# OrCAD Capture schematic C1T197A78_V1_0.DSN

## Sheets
1 01_Log: title: Telink-Semi; rev: V1.0; note: C1T197A78
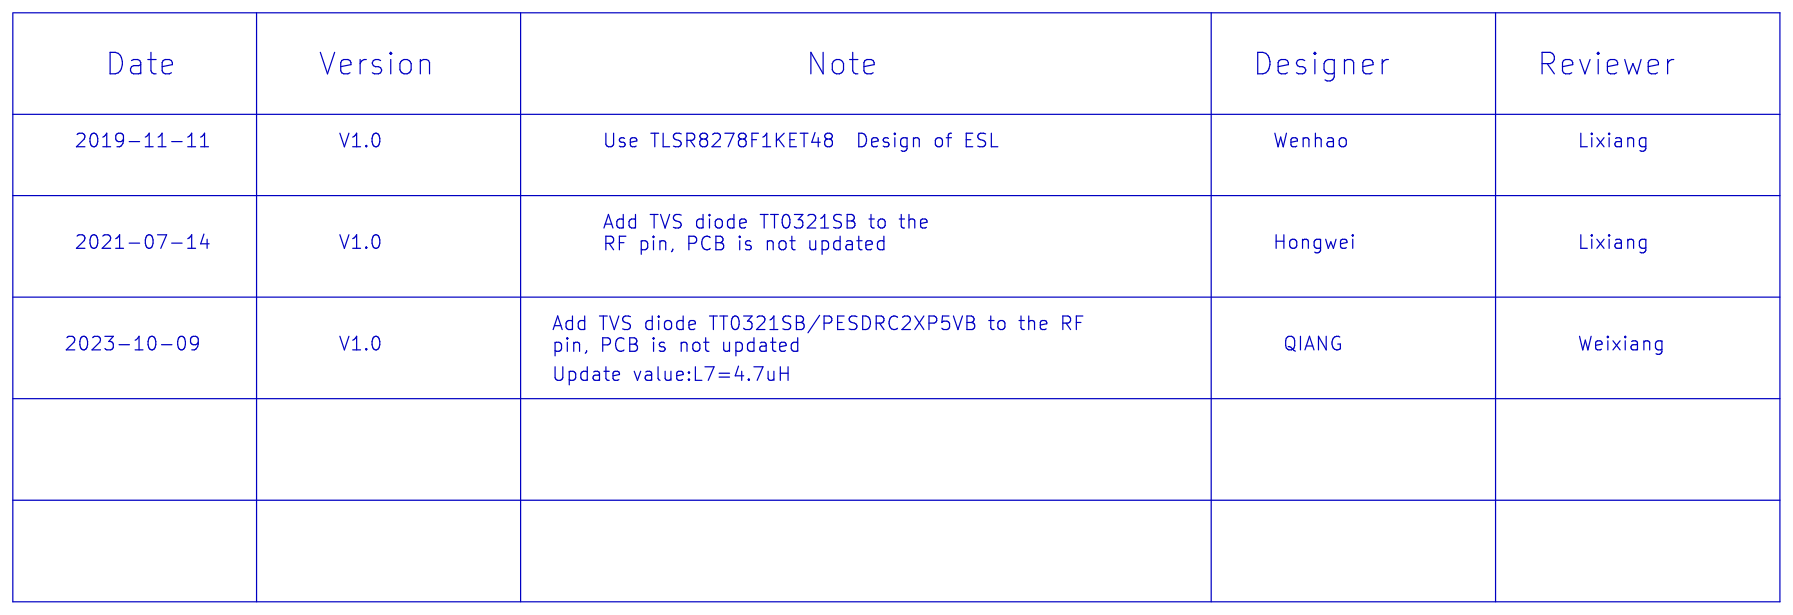
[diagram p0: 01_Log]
2 02_Main: size A4
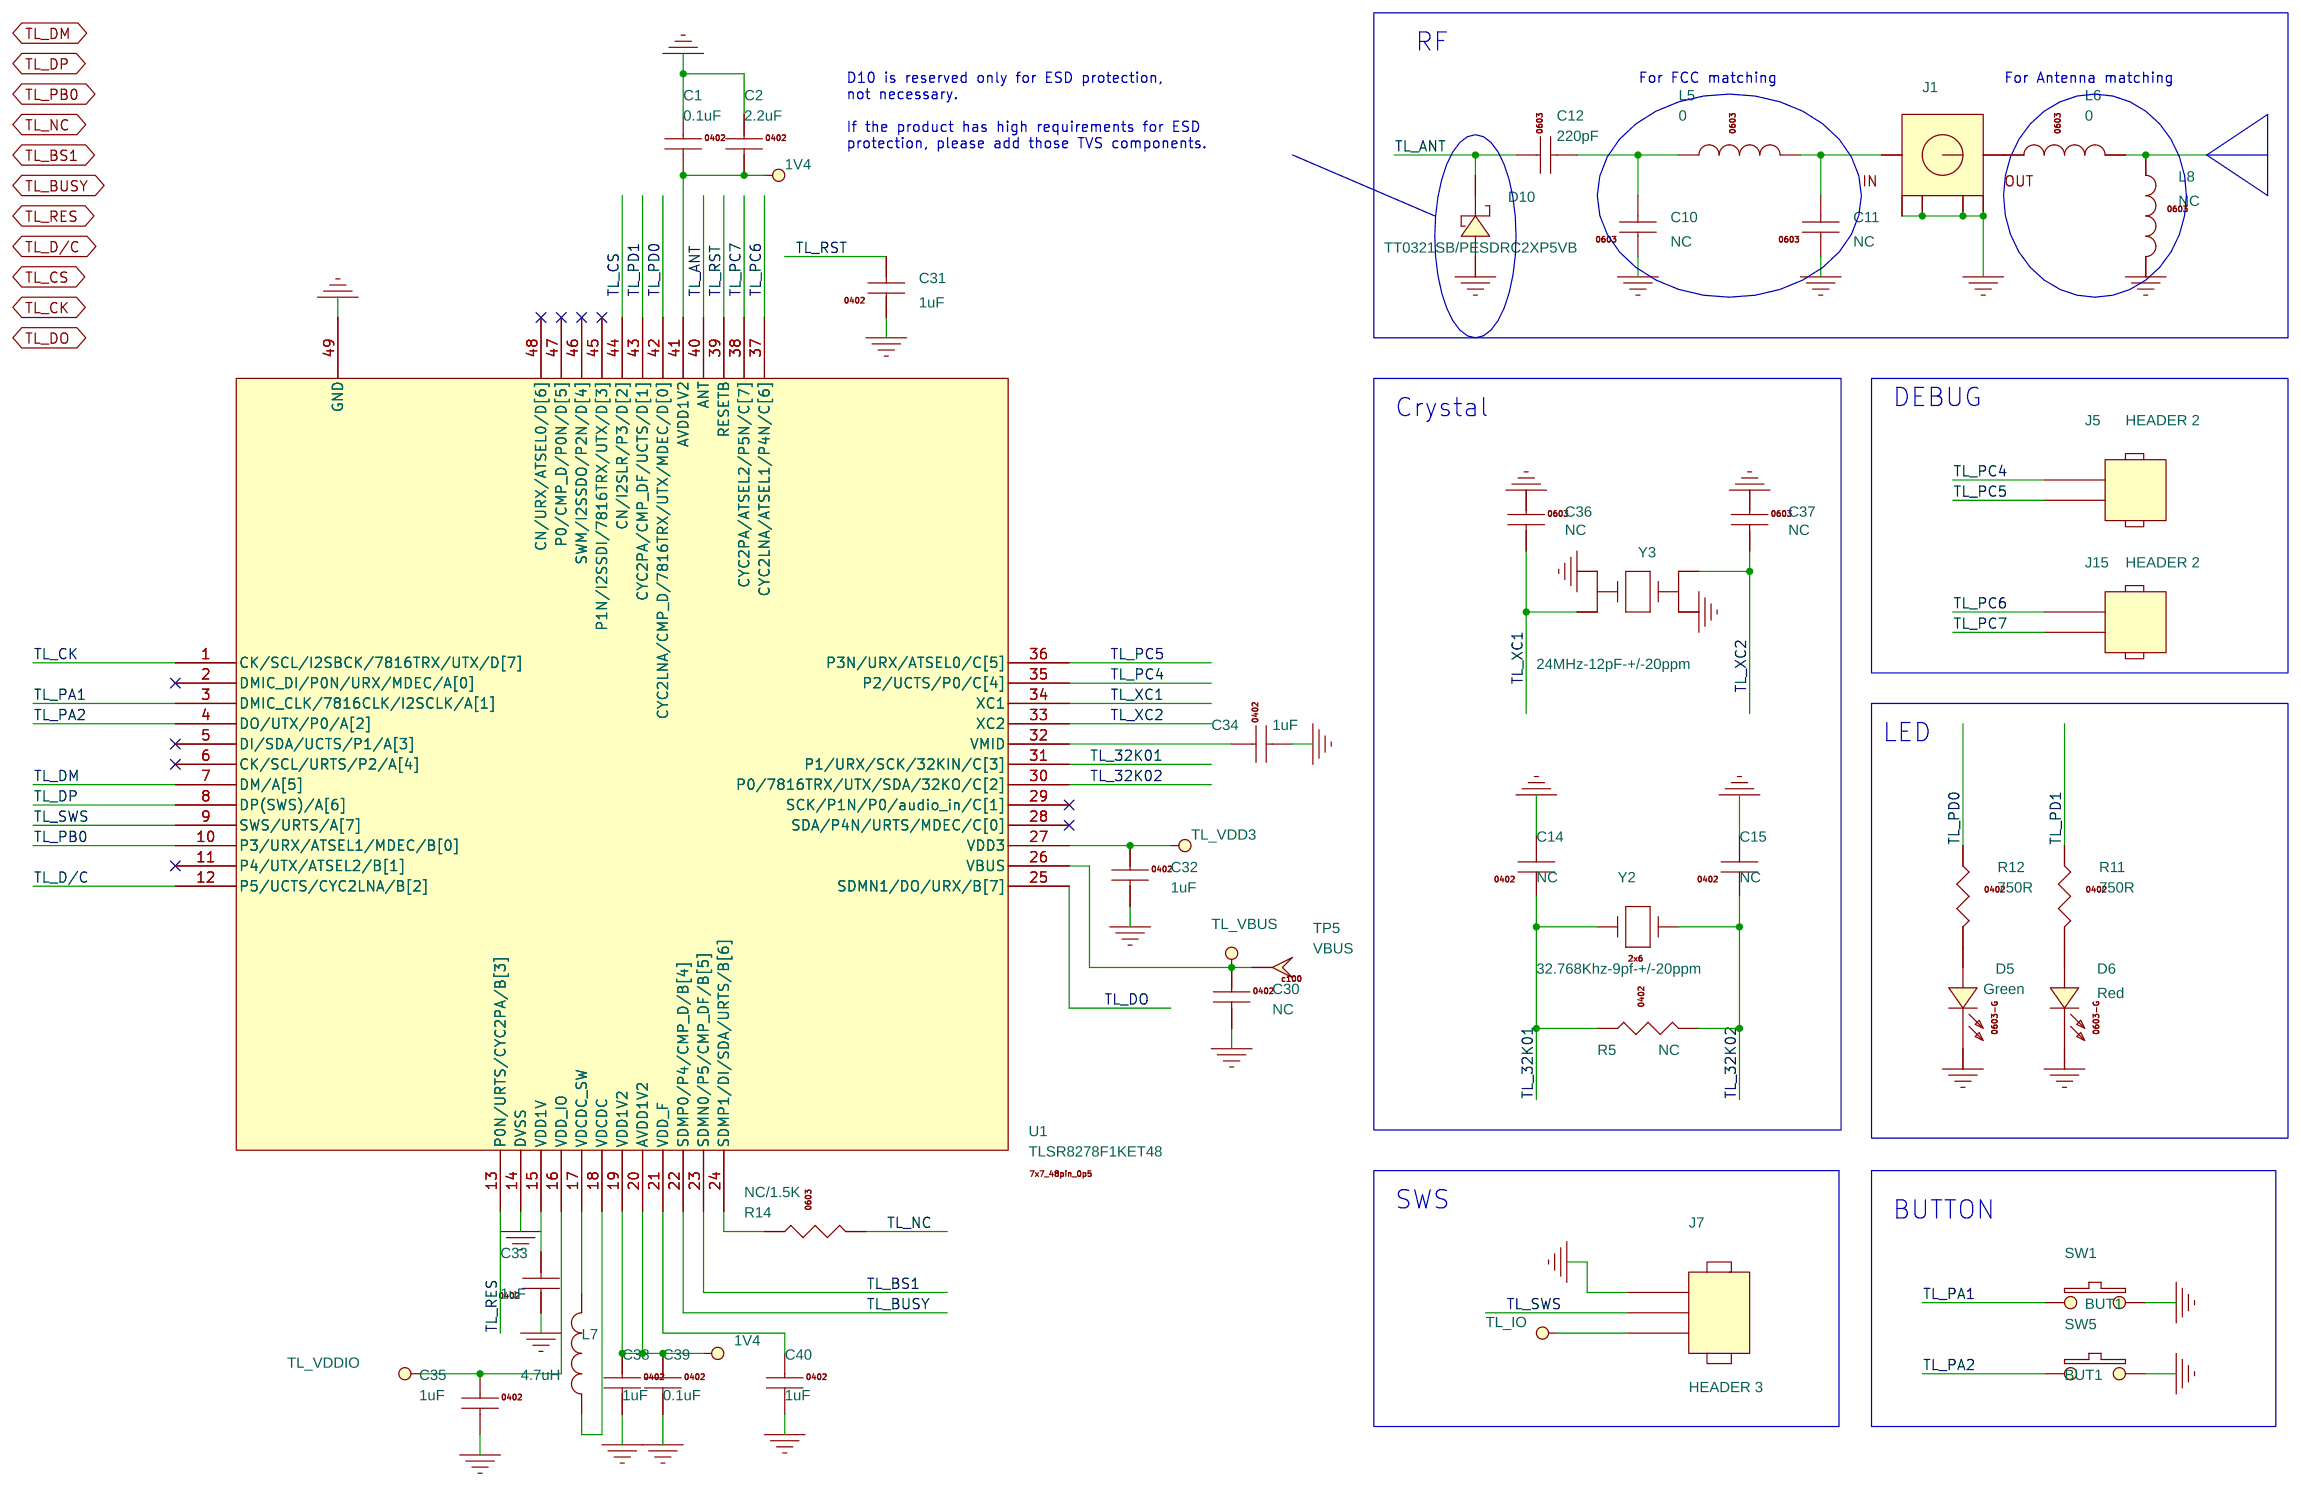
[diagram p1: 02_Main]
3 03_Display: size A4
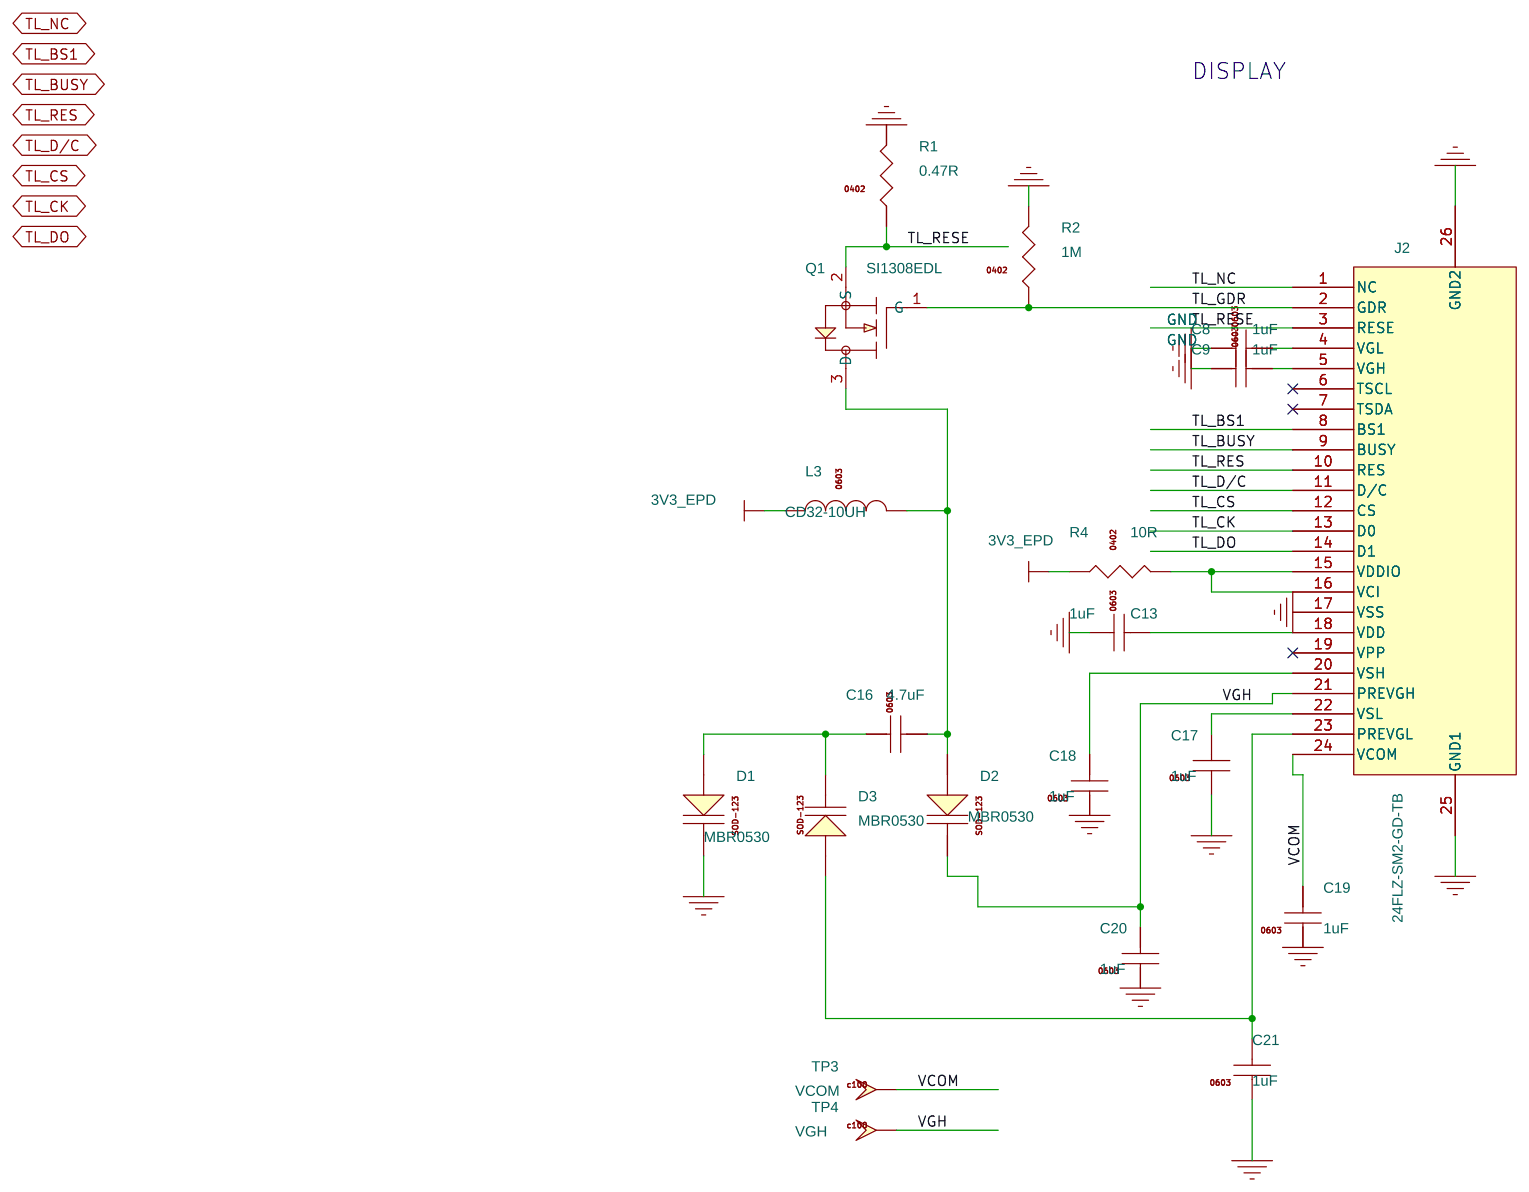
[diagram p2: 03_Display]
4 04_Power: size A4
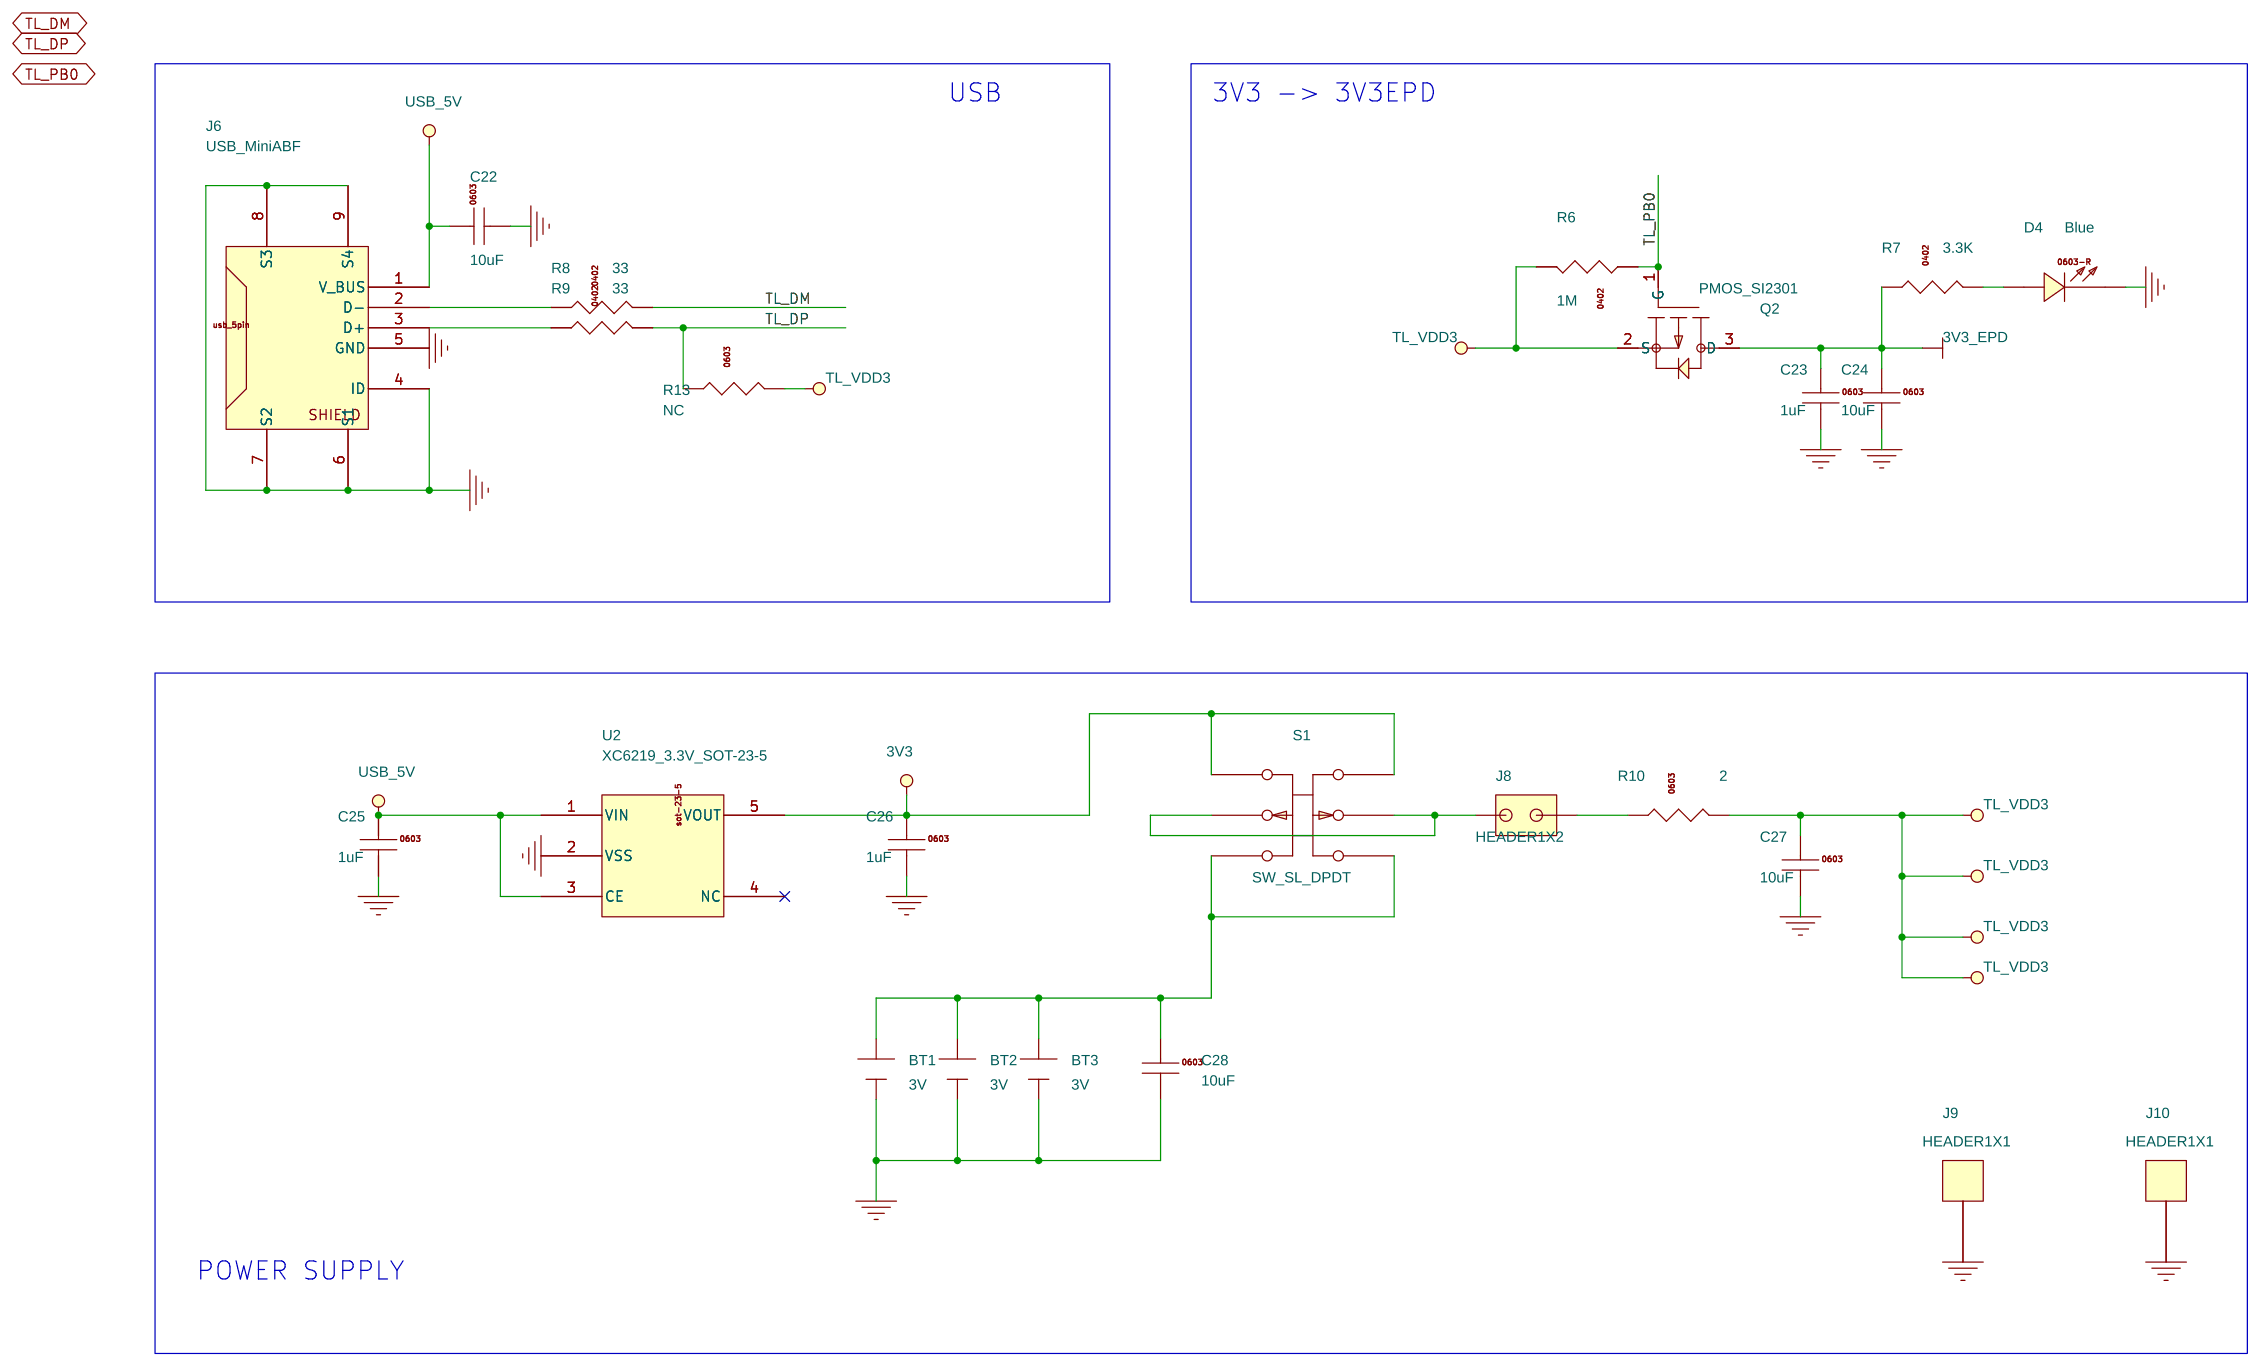
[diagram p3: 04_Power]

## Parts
sheet 02_Main
C1  0.1uF  [0402]
C2  2.2uF  [0402]
C10  NC  [0402]
C11  NC  [0402]
C12  220pF  [0402]
C14  NC  [0402]
C15  NC  [0402]
C30  NC  [0402]
C31  1uF  [0402]
C32  1uF  [0402]
C33  1uF  [0402]
C34  1uF  [0402]
C35  1uF  [0402]
C36  NC  [0402]
C37  NC  [0402]
C38  1uF  [0402]
C39  0.1uF  [0402]
C40  1uF  [0402]
D5  Green  [0603-LED]
D6  Red  [0603-LED]
D10  TT0321SB/PESDRC2XP5VB  [SOD-123]
J1  MM8130  [MM8130-2600]
J5  HEADER 2  [HDR254F-1X2X850]
J7  HEADER 3  [HDR254F-1X3X850]
J15  HEADER 2  [HDR254F-1X2X850]
L5  0  [0402]
L6  0  [0402]
L7  4.7uH  [2x2_5mm]
L8  NC  [0402]
R5  NC  [0402]
R11  750R  [0402]
R12  750R  [0402]
R14  NC/1.5K  [0402]
SW1  BUT1  [butsmd2px4_00y3_00_nh]
SW5  BUT1  [butsmd2px4_00y3_00_nh]
TP5  VBUS  [TP100]
U1  TLSR8278F1KET48  [qfn_7x7_48pin_0p5_4p20x4p20]
Y2  32.768Khz-9pf-+/-20ppm  [OSC_2x6]
Y3  24MHz-12pF-+/-20ppm  [OSCCC250X320X110]
sheet 03_Display
C8  1uF  [0603C]
C9  1uF  [0603C]
C13  1uF  [0402]
C16  4.7uF  [0805C]
C17  1uF  [0603C]
C18  1uF  [0603C]
C19  1uF  [0603C]
C20  1uF  [0603C]
C21  1uF  [0603C]
D1  MBR0530  [sod-123]
D2  MBR0530  [sod-123]
D3  MBR0530  [sod-123]
J2  24FLZ-SM2-GD-TB  [fpc_24pin]
L3  CD32-10UH  [cd32]
Q1  SI1308EDL  [sot-323]
R1  0.47R  [0603r]
R2  1M  [0402]
R4  10R  [0402]
TP3  VCOM  [TP100]
TP4  VGH  [TP100]
sheet 04_Power
BT1  3V  [BAT]
BT2  3V  [BAT]
BT3  3V  [BAT]
C22  10uF  [0603C]
C23  1uF  [0603C]
C24  10uF  [0603C]
C25  1uF  [0603C]
C26  1uF  [0402]
C27  10uF  [0603C]
C28  10uF  [0805C]
D4  Blue  [0603-LED]
J6  USB_MiniABF  [USB-MINI-F5]
J8  HEADER1X2  [HDR254F-1X2X850]
J9  HEADER1X1  [HDR254F-1X1X850]
J10  HEADER1X1  [HDR254F-1X1X850]
Q2  PMOS_SI2301  [mos_sot-23]
R6  1M  [0603r]
R7  3.3K  [0603r]
R8  33  [0402]
R9  33  [0402]
R10  2  [0603R]
R13  NC  [0402]
S1  SW_SL_DPDT  [sw]
U2  XC6219_3.3V_SOT-23-5  [sot-23-5]

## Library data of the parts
C1 C2 C14 C15 C30 C32 C34 C35 C38-C40 = C1005X5R1C104K
C10-C13 C16-C21 C36 C37 = C1608_NC
C31 C33 = C1005X5R1C105K
D5 D6 = 0603D_Green
D10 = DIODE_SCHOTTKY_0
J1 = MM8130_1
J5 J15 = HEADER_2
J7 = HEADER_3
L5 L6 L8 = MLK1608_000R
L7 = IND_0
R5 = RS0402_NC
R11 R12 = RS0402K102JT
R13 R14 = RS0603K152JT
SW1 SW5 = SW_PUSHBUTTON-SPST_SM
TP3-TP5 = TestPad100
U1 = TLSR8278F1KET48_2
Y2 = OSC_2x6_2pin
Y3 = CRYSTAL4_SM_0
C8 C9 C22-C26 = C1608X5R1C105M
D1-D3 = Diode_CDBW0520L-G
J2 = CON_2.54mm_1x24
L3 = MLK1608S4N7ST
Q1 = NMOS_SI2302
R1 R2 R4 = RS0402K000JT
BT1-BT3 = BATTERY_2xAAA_1
C27 C28 = C1608X5R0J106M
D4 = 0603D_Red
J6 = USB_MiniABF_5pin
J8 = B2S_3: PAGE: POWER
J9 J10 = CON1
Q2 = PMOS_SI2301
R6 = RS0402K105JT
R7 = RS0402K332JT
R8 R9 = RS0402K330JT
R10 = RS0603K020JT
S1 = SW_SL_DPDT_0
U2 = XC6219_0.3V_SOT-23-5

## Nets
1V4: C1.2 C2.2 C38.1 C39.1 U1.19(VDD1V2) U1.20(AVDD1V2) U1.41(AVDD1V2)
3V3: C26.1 S1.1 S1.6 U2.5(VOUT)
3V3_EPD: C23.1 C24.1 L3.1 Q2.3(D) R4.1 R7.1
GND: BT1.2(-) BT2.2(-) BT3.2(-) C1.1 C2.1 C8.1 C9.1 C10.1 C11.1 C13.1 C14.2 C15.2 C17.1 C18.1 C19.1 C20.1 C21.1 C22.2 C23.2 C24.2 C25.2 C26.2 C27.2 C28.2 C30.2 C31.1 C32.2 C33.1 C34.2 C35.2 C36.1 C37.1 C38.2 C39.2 C40.2 D1.C D4.C(CATHODE) D5.C(CATHODE) D6.C(CATHODE) D10.A(ANODE) J1.3 J1.4 J1.5 J1.6 J2.17(VSS) J2.25(GND1) J2.26(GND2) J6.4(ID) J6.5(GND) J6.6(S1) J6.7(S2) J6.8(S3) J6.9(S4) J7.3 J9.1 J10.1 L8.2 R1.2 R2.2 SW1.2 SW5.2 U1.14(DVSS) U1.49(GND) U2.2(VSS) Y3.2 Y3.4
TL_3V3: C27.1 C32.1 C35.1 J7.1 Q2.2(S) R6.2 R10.2 R13.2 U1.16(VDD_IO) U1.27(VDD3)
TL_32K01: C14.1 R5.1 U1.31(P1/URX/SCK/32KIN/C[3]) Y2.2
TL_32K02: C15.1 R5.2 U1.30(P0/7816TRX/UTX/SDA/32KO/C[2]) Y2.1
TL_ANT: C12.1 D10.C(CATHODE) U1.40(ANT)
TL_BS1: U1.23(SDMN0/P5/CMP_DF/B[5])
TL_BS1 (page 03_Display): J2.8(BS1)
TL_BUSY: U1.22(SDMP0/P4/CMP_D/B[4])
TL_BUSY (page 03_Display): J2.9(BUSY)
TL_CK: U1.1(CK/SCL/I2SBCK/7816TRX/UTX/D[7])
TL_CK (page 03_Display): J2.13(D0)
TL_CS: U1.44(CN/I2SLR/P3/D[2])
TL_CS (page 03_Display): J2.12(CS)
TL_D/C: U1.12(P5/UCTS/CYC2LNA/B[2])
TL_D/C (page 03_Display): J2.11(D/C)
TL_DM: U1.7(DM/A[5])
TL_DM (page 04_Power): R8.2
TL_DO: U1.25(SDMN1/DO/URX/B[7])
TL_DO (page 03_Display): J2.14(D1)
TL_DP: U1.8(DP(SWS)/A[6])
TL_DP (page 04_Power): R9.2 R13.1
TL_GDR: J2.2(GDR) Q1.1(G) R2.1
TL_NC: R14.2
TL_NC (page 03_Display): J2.1(NC)
TL_PA1: SW1.1 U1.3(DMIC_CLK/7816CLK/I2SCLK/A[1])
TL_PA2: SW5.1 U1.4(DO/UTX/P0/A[2])
TL_PB0: U1.10(P3/URX/ATSEL1/MDEC/B[0])
TL_PB0 (page 04_Power): Q2.1(G) R6.1
TL_PC4: J5.2 U1.35(P2/UCTS/P0/C[4])
TL_PC5: J5.1 U1.36(P3N/URX/ATSEL0/C[5])
TL_PC6: J15.2 U1.37(CYC2LNA/ATSEL1/P4N/C[6])
TL_PC7: J15.1 U1.38(CYC2PA/ATSEL2/P5N/C[7])
TL_PD0: R12.1 U1.42(CYC2LNA/CMP_D/7816TRX/UTX/MDEC/D[0])
TL_PD1: R11.1 U1.43(CYC2PA/CMP_DF/UCTS/D[1])
TL_RES: U1.13(P0N/URTS/CYC2PA/B[3])
TL_RES (page 03_Display): J2.10(RES)
TL_RESE: J2.3(RESE) Q1.2(S) R1.1
TL_RST: C31.2 U1.39(RESETB)
TL_SWS: J7.2 U1.9(SWS/URTS/A[7])
TL_VBUS: C30.1 TP5.1(TP) U1.26(VBUS)
TL_XC1: C36.2 U1.34(XC1) Y3.3
TL_XC2: C37.2 U1.33(XC2) Y3.1
USB_5V: C22.1 C25.1 J6.1(V_BUS) U2.1(VIN) U2.3(CE)
VCOM: C19.2 J2.24(VCOM) TP3.1(TP)
VGH: C20.2 D2.C J2.21(PREVGH) TP4.1(TP)
N14795340: BT1.1(+) BT2.1(+) BT3.1(+) C28.1 S1.3 S1.4
N14807043: J6.3(D+) R9.1
N14807063: J6.2(D-) R8.1
N14807393: D4.A(ANODE) R7.2
N14811368: J8.1 S1.2 S1.5
N14834347: J8.2 R10.1
N14862027: C13.2 J2.18(VDD)
N14862131: J2.15(VDDIO) J2.16(VCI) R4.2
N14862139: C8.2 J2.4(VGL)
N14862151: C9.2 J2.5(VGH)
N14862215: C21.2 D3.A J2.23(PREVGL)
N14862243: C17.2 J2.22(VSL)
N14862263: C18.2 J2.20(VSH)
N14862345: C16.2 D2.A L3.2 Q1.3(D)
N14862353: C16.1 D1.A D3.C
N14937524: C10.2 C12.2 L5.1
N14941034: C34.1 U1.32(VMID)
N14941094: C33.2 U1.15(VDD1V)
N14941130: L7.1 U1.18(VDCDC)
N14941146: L7.2 U1.17(VDCDC_SW)
N14941234: C40.1 U1.21(VDD_F)
N14941494: R14.1 U1.24(SDMP1/DI/SDA/URTS/B[6])
N14949497: L6.2 L8.1
N14951149: C11.2 J1.1 L5.2
N14951903: D6.A(ANODE) R11.2
N14951904: D5.A(ANODE) R12.2
N14955257: J1.2 L6.1

Not connected (* = marked no-connect by the designer): J2 6(TSCL)* 7(TSDA)* 19(VPP)*; U1 2(DMIC_DI/P0N/URX/MDEC/A[0])* 5(DI/SDA/UCTS/P1/A[3])* 6(CK/SCL/URTS/P2/A[4])* 11(P4/UTX/ATSEL2/B[1])* 28(SDA/P4N/URTS/MDEC/C[0])* 29(SCK/P1N/P0/audio_in/C[1])* 45(P1N/I2SSDI/7816TRX/UTX/D[3])* 46(SWM/I2SSDO/P2N/D[4])* 47(P0/CMP_D/P0N/D[5])* 48(CN/URX/ATSEL0/D[6])*; U2 4(NC)*

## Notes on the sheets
sheet 1
- Date
- Version
- Note
- Designer
- Reviewer
- 2019-11-11
- V1.0
- Use TLSR8278F1KET48  Design of ESL
- Wenhao
- Lixiang
- 2021-07-14
- V1.0
- Add TVS diode TT0321SB to the
  RF pin, PCB is not updated
- Hongwei
- Lixiang
- Add TVS diode TT0321SB/PESDRC2XP5VB to the RF
  pin, PCB is not updated
- 2023-10-09
- V1.0
- QIANG
- Weixiang
- Update value:L7=4.7uH
sheet 2
- RF
- D10 is reserved only for ESD protection,
  not necessary.
  If the product has high requirements for ESD
  protection, please add those TVS components.
- For FCC matching
- For Antenna matching
- Crystal
- DEBUG
- LED
- SWS
- BUTTON
sheet 3
- DISPLAY
sheet 4
- USB
- 3V3 -> 3V3EPD
- POWER SUPPLY
